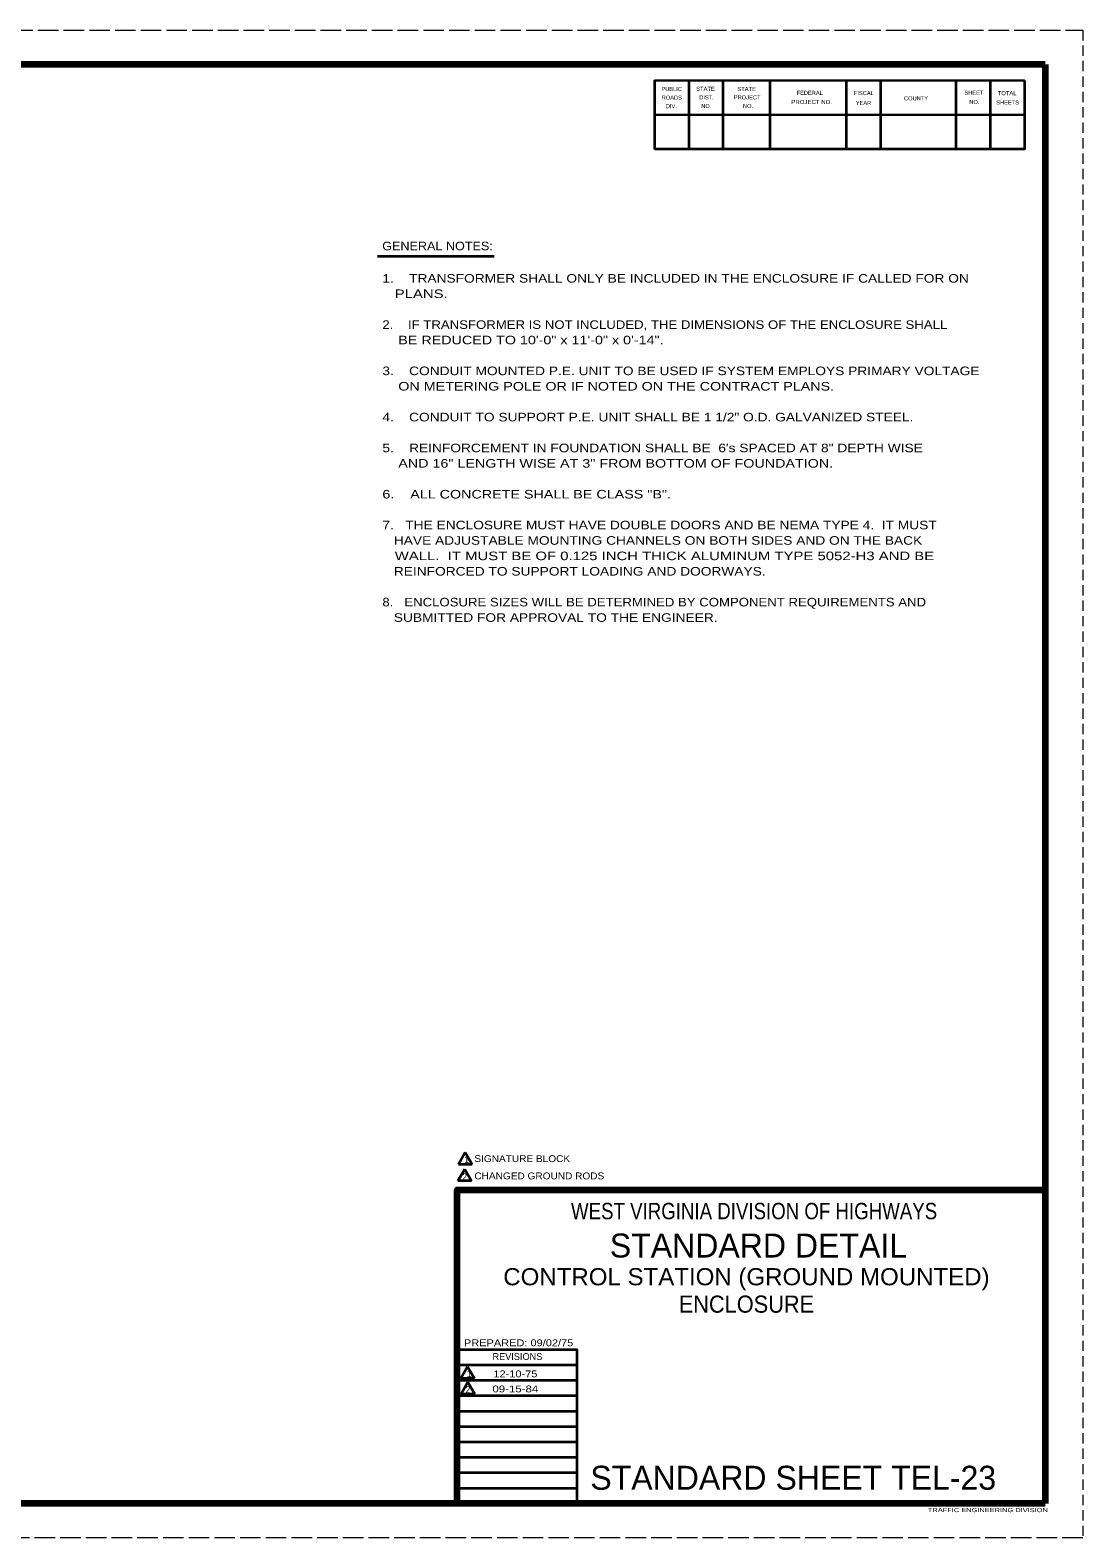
# Model space of a CAD drawing. Extents: x -1 to 679, y 0 to 440.
# Drawn here: x 371.3 to 678.6, y -0.1 to 440 of the extents above; entities that cross this region are included whole.
import ezdxf
from ezdxf.enums import TextEntityAlignment as Align

# ---------------------------------------------------------------- set-up
doc = ezdxf.new("R2010")
doc.units = 0
doc.linetypes.add('LONG_DASHED', pattern=[7.5, 6, -1.5])
doc.linetypes.add('MEDIUM_DASHED', pattern=[4.5, 3, -1.5])
doc.layers.add('1', color=7, linetype='Continuous', lineweight=53)
doc.layers.add('61', color=7, linetype='Continuous', lineweight=35)

msp = doc.modelspace()

# ---------------------------------------------------------------- linework, layer by layer
at = {"layer": '1', "linetype": 'MEDIUM_DASHED', "lineweight": 13}
msp.add_line((678.589, 439.961), (678.569, -0.059), dxfattribs=at)
at = {"layer": '1', "lineweight": 35}
for p, q in [((472.64, 374.043), (506.707, 374.043)), ((498.322, 112.351), (496.322, 108.887)), ((498.322, 112.351), (500.322, 108.887)), ((498.156, 107.542), (496.156, 104.078)), ((500.322, 108.887), (496.322, 108.887)), ((498.156, 107.542), (500.156, 104.078)), ((500.156, 104.078), (496.156, 104.078)), ((530.969, 50.361), (495.989, 50.361)), ((498.983, 49.847), (496.983, 46.383)), ((498.983, 49.847), (500.983, 46.383)), ((530.969, 45.861), (495.989, 45.861)), ((500.983, 46.383), (496.983, 46.383)), ((499.082, 45.355), (497.082, 41.891)), ((499.082, 45.355), (501.082, 41.891)), ((530.969, 41.361), (495.989, 41.361)), ((501.082, 41.891), (497.082, 41.891)), ((530.969, 36.841), (495.989, 36.841)), ((530.969, 32.361), (495.989, 32.361)), ((530.969, 27.881), (495.989, 27.881)), ((530.969, 23.381), (495.989, 23.381)), ((530.969, 18.881), (495.989, 18.881)), ((530.969, 14.361), (495.989, 14.361))]:
    msp.add_line(p, q, dxfattribs=at)
at = {"layer": '1', "lineweight": 158}
msp.add_lwpolyline([(495.969, 9.921), (495.969, 101.501), (667.629, 101.501)], dxfattribs=at)
at = {"layer": '1', "lineweight": 35}
msp.add_lwpolyline([(530.969, 9.881), (530.969, 54.841), (495.989, 54.841)], dxfattribs=at)
at = {"layer": '61', "linetype": 'LONG_DASHED', "lineweight": 13}
for p, q in [((-1.431, 439.961), (678.589, 439.961)), ((678.569, -0.059), (-1.491, -0.079))]:
    msp.add_line(p, q, dxfattribs=at)
at = {"layer": '61', "lineweight": 158}
for p, q in [((667.609, 429.961), (667.629, 9.921)), ((667.629, 9.921), (28.569, 9.941))]:
    msp.add_line(p, q, dxfattribs=at)
at = {"layer": '61'}
for p, q in [((563.529, 425.201), (563.529, 405.201)), ((573.529, 425.201), (573.529, 405.201)), ((587.209, 425.201), (587.209, 405.201)), ((609.529, 425.201), (609.529, 405.201)), ((619.529, 425.201), (619.529, 405.201)), ((641.509, 425.221), (641.509, 405.221)), ((651.509, 425.221), (651.509, 405.221)), ((661.529, 415.181), (553.509, 415.201))]:
    msp.add_line(p, q, dxfattribs=at)
at = {"layer": '61', "lineweight": 158}
msp.add_lwpolyline([(667.609, 429.961), (28.569, 429.961), (28.569, 9.941)], dxfattribs=at)
at = {"layer": '61'}
for points in [[(661.509, 425.221), (553.529, 425.201), (553.529, 405.201)], [(661.509, 425.221), (661.509, 405.221), (553.529, 405.201)]]:
    msp.add_lwpolyline(points, dxfattribs=at)

# ---------------------------------------------------------------- texts
at = {"layer": '1'}
for s, height, width, p in [('GENERAL NOTES:', 2.5, 1.1, (490.209, 375.722)), ('WEST VIRGINIA DIVISION OF HIGHWAYS', 4.795, 0.85, (582.617, 92.901)), ('CONTROL STATION (GROUND MOUNTED)', 5, 1.05, (580.382, 73.635)), ('ENCLOSURE', 5, 0.95, (580.382, 65.635)), ('12-10-75', 2, 1.2, (512.938, 46.781)), ('09-15-84', 2, 1.25, (512.918, 42.381))]:
    msp.add_text(s, height=height, dxfattribs=dict(at, width=width)).set_placement(p, align=Align.CENTER)
for s, height, width, p in [('1.    TRANSFORMER SHALL ONLY BE INCLUDED IN THE ENCLOSURE IF CALLED FOR ON', 2.5, 1.2, (474.104, 366.271)), ('   PLANS.', 2.5, 1.3, (474.104, 361.771)), ('2.    IF TRANSFORMER IS NOT INCLUDED, THE DIMENSIONS OF THE ENCLOSURE SHALL', 2.5, 1.15, (474.104, 352.771)), ('    BE REDUCED TO 10\'-0" x 11\'-0" x 0\'-14".', 2.5, 1.25, (474.104, 348.271)), ('3.    CONDUIT MOUNTED P.E. UNIT TO BE USED IF SYSTEM EMPLOYS PRIMARY VOLTAGE', 2.5, 1.2, (474.104, 339.271)), ('    ON METERING POLE OR IF NOTED ON THE CONTRACT PLANS.', 2.5, 1.25, (474.104, 334.771)), ('4.    CONDUIT TO SUPPORT P.E. UNIT SHALL BE 1 1/2" O.D. GALVANIZED STEEL.', 2.5, 1.2, (474.104, 325.771)), ('5.    REINFORCEMENT IN FOUNDATION SHALL BE  6\'s SPACED AT 8" DEPTH WISE', 2.5, 1.2, (474.104, 316.771)), ('    AND 16" LENGTH WISE AT 3" FROM BOTTOM OF FOUNDATION.', 2.5, 1.25, (474.104, 312.271)), ('6.    ALL CONCRETE SHALL BE CLASS "B".', 2.5, 1.25, (474.104, 303.271)), ('7.   THE ENCLOSURE MUST HAVE DOUBLE DOORS AND BE NEMA TYPE 4.  IT MUST', 2.5, 1.2, (474.104, 294.271)), ('   HAVE ADJUSTABLE MOUNTING CHANNELS ON BOTH SIDES AND ON THE BACK', 2.5, 1.2, (474.104, 289.771)), ('   WALL.  IT MUST BE OF 0.125 INCH THICK ALUMINUM TYPE 5052-H3 AND BE', 2.5, 1.3, (474.104, 285.271)), ('   REINFORCED TO SUPPORT LOADING AND DOORWAYS.', 2.5, 1.2, (474.104, 280.771)), ('8.   ENCLOSURE SIZES WILL BE DETERMINED BY COMPONENT REQUIREMENTS AND', 2.5, 1.15, (474.104, 271.771)), ('   SUBMITTED FOR APPROVAL TO THE ENGINEER.', 2.5, 1.2, (474.104, 267.271)), ('SIGNATURE BLOCK', 2, 1.1, (500.958, 109.595)), ('2', 2, 0.9, (497.487, 104.314)), ('2', 2, 0.9, (497.487, 104.314)), ('2', 2, 0.9, (497.487, 104.314)), ('CHANGED GROUND RODS', 2, 1.1, (500.958, 104.562)), ('PREPARED: 09/02/75', 1.998, 1.2, (497.929, 55.841)), ('2', 2, 0.9, (498.392, 42.159)), ('TRAFFIC ENGINEERING DIVISION', 1.2, 1.35, (633.349, 7.421))]:
    msp.add_text(s, height=height, dxfattribs=dict(at, width=width)).set_placement(p)
for s, height, p in [('1', 2, (497.983, 109.347)), ('REVISIONS', 1.998, (506.249, 51.841)), ('1', 2, (498.694, 46.808)), ('STANDARD SHEET TEL-23', 6.993, (534.809, 13.961))]:
    msp.add_text(s, height=height, dxfattribs=at).set_placement(p)
msp.add_text('STANDARD DETAIL', height=6.993, dxfattribs=at).set_placement((583.886, 81.741), align=Align.CENTER)
at = {"layer": '61'}
for s, rotation, p in [('PUBLIC', 0.033, (555.569, 422.181)), ('ROADS', 0.124, (555.649, 419.661)), ('DIV.', 359.932, (556.849, 417.161)), ('DIST.', 0.056, (566.609, 419.741)), ('FEDERAL', 0.007, (595.029, 421.061)), ('FISCAL', 359.942, (611.769, 421.001)), ('YEAR', 0.105, (612.289, 418.101)), ('COUNTY', 0.069, (626.389, 419.461)), ('SHEET', 0.059, (644.029, 421.121)), ('SHEETS', 359.959, (653.309, 418.281))]:
    msp.add_text(s, height=1.201, rotation=rotation, dxfattribs=at).set_placement(p)
for s, rotation, width, p in [('STATE', 0.059, 1.05, (565.729, 422.241)), ('STATE', 0.059, 1.05, (577.729, 422.181)), ('NO.', 359.852, 0.95, (567.189, 417.221)), ('PROJECT', 359.908, 1.05, (576.649, 419.761)), ('NO.', 0.225, 0.95, (579.389, 417.221)), ('PROJECT NO.', 359.922, 1.1, (593.489, 418.401)), ('NO.', 359.852, 0.95, (645.449, 418.401)), ('TOTAL', 359.926, 1.05, (653.769, 420.981))]:
    msp.add_text(s, height=1.201, rotation=rotation, dxfattribs=dict(at, width=width)).set_placement(p)

doc.saveas('drawing.dxf')
